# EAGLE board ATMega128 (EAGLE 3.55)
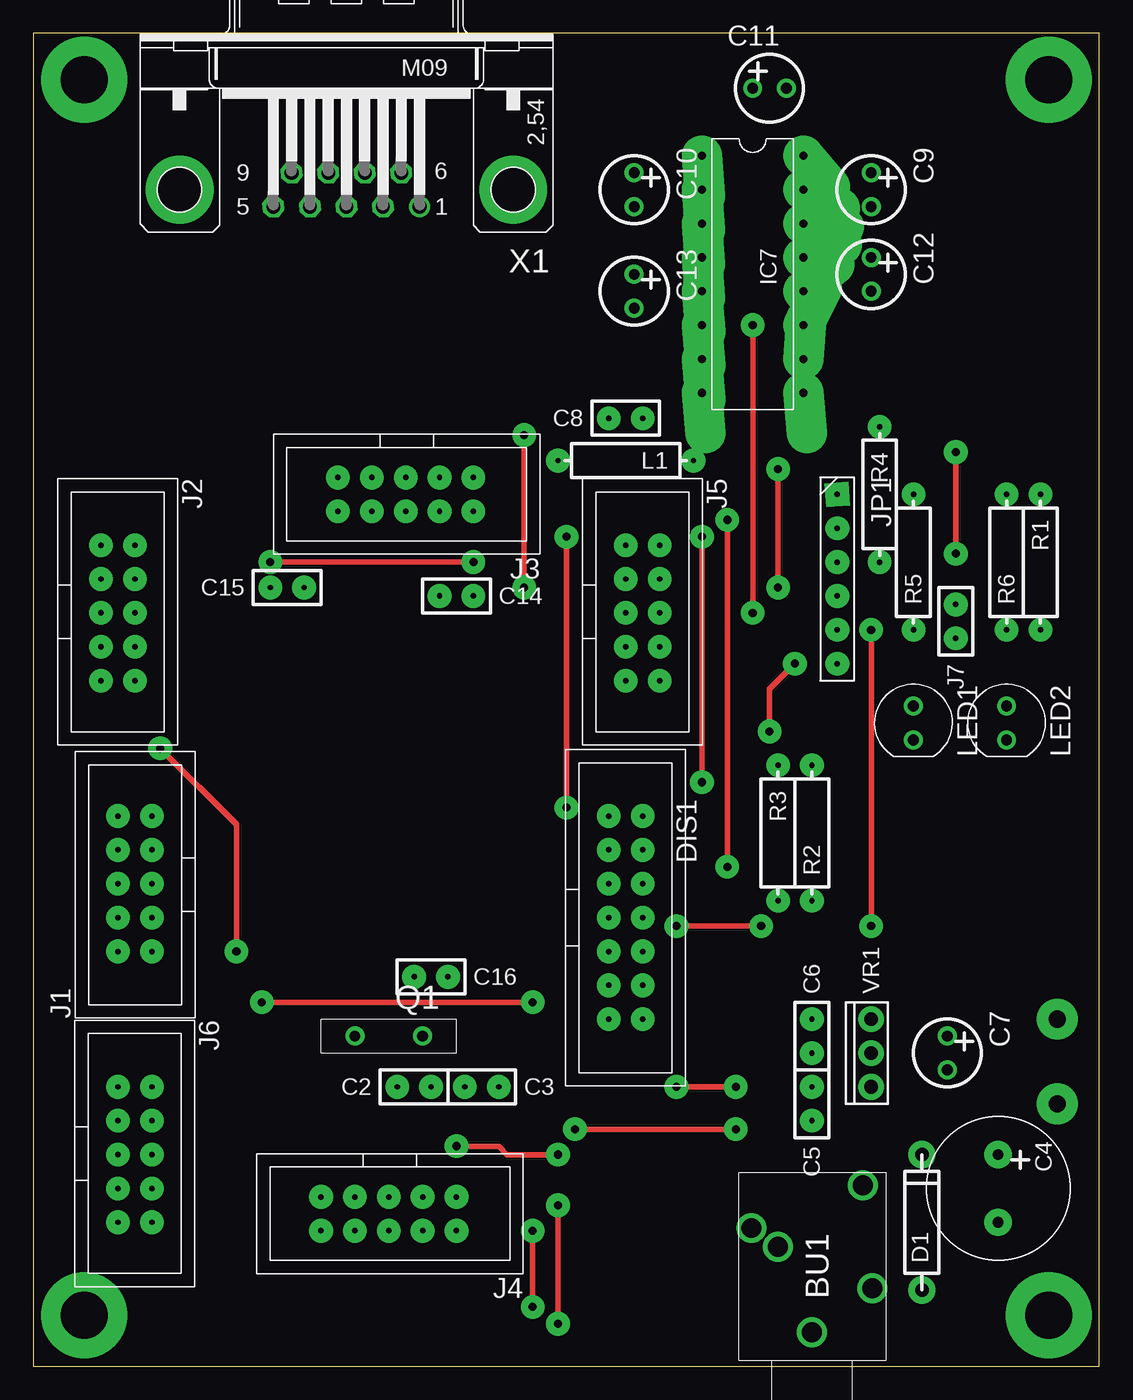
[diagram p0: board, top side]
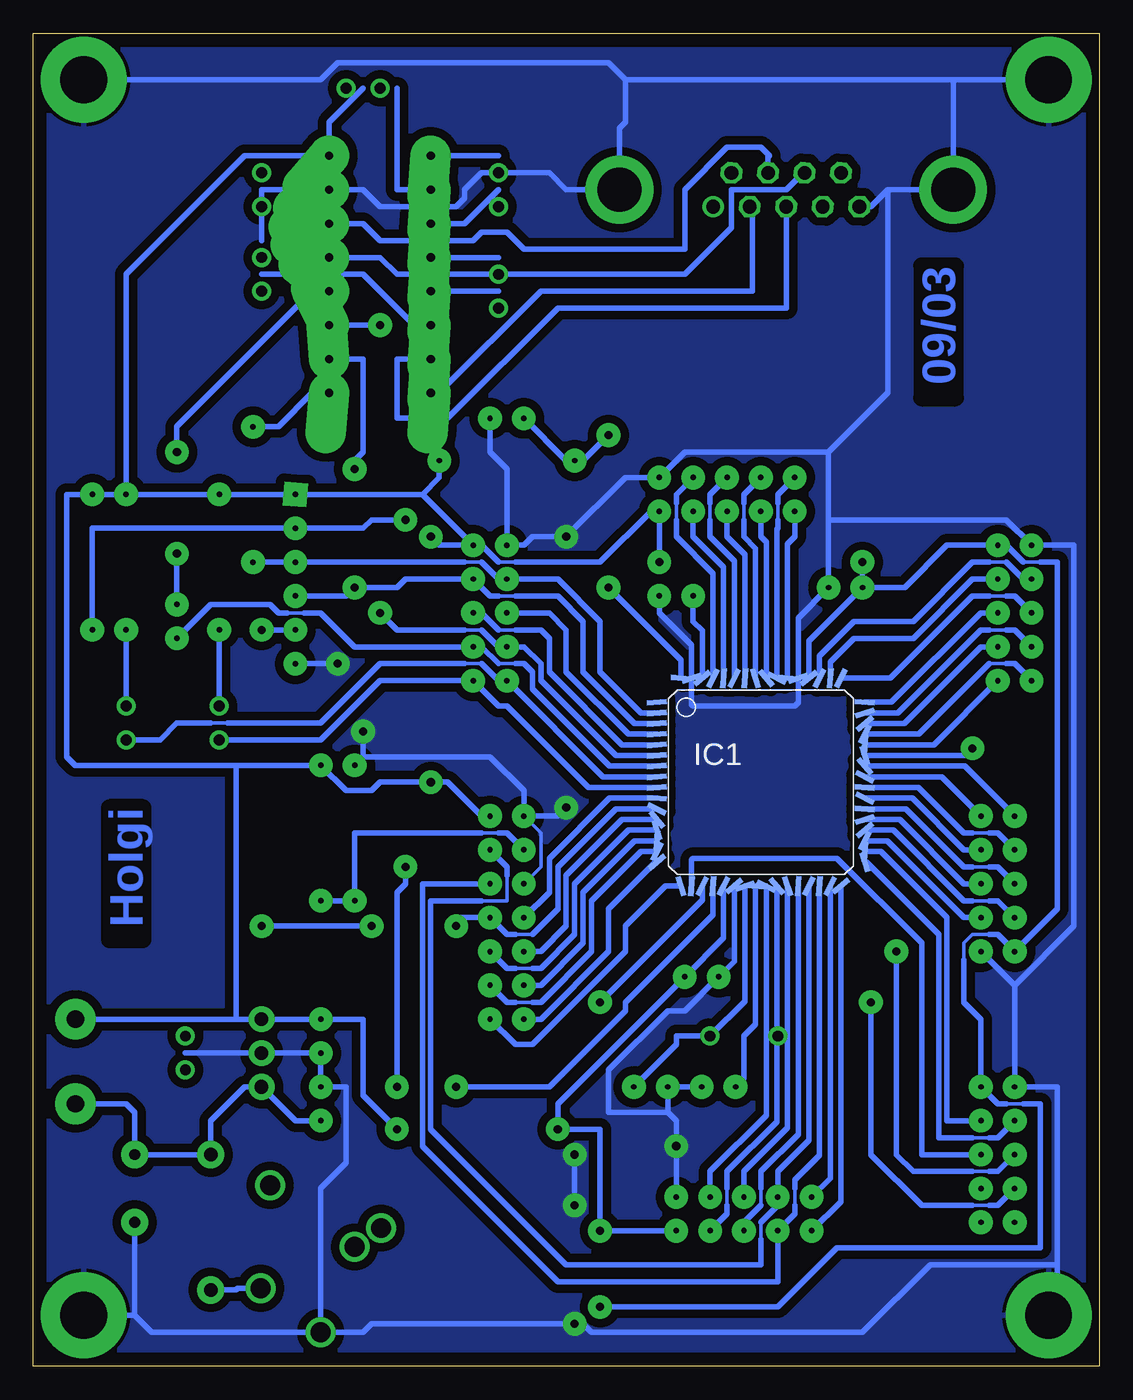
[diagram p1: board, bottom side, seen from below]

Size 79.99 x 100 mm. Coordinates in mm from the lower left corner, seen from the top.
Outline: 0,0 79.99,0 79.99,100 0,100 0,0
Copper layers used: Top, Bottom

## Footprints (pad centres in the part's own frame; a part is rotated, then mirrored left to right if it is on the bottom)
_3,5MM = drill 1.499 pad 2.184 round:  0,0;  3.302,-4.521;  7.823,4.521;  6.401,2.54;  11.024,-3.81
RM2,5 = drill 0.406 pad 1.778 round:  -1.27,0;  1.27,0
KO02 = drill 0.813 pad 2.032 round:  -2.54,0;  2.54,0
KO01 = drill 0.813 pad 1.422 round:  0,0;  2.54,0
O_1A = drill 1.016 pad 2.032 round:  -5.08,0;  5.08,0
7 = drill 0.406 pad 1.778 round:  0,0;  2.54,0;  5.08,0;  7.62,0;  10.16,0;  10.16,2.54;  7.62,2.54;  5.08,2.54;  2.54,2.54;  0,2.54;  12.7,0;  12.7,2.54;  15.24,0;  15.24,2.54
FP64 = smd 1.5 x 0.4 rotated 4.9:  -7.8,0.4 | smd 1.5 x 0.4 rotated 4.8:  -7.8,1.2 | smd 1.5 x 0.4 rotated 5:  -7.8,-0.4 | smd 1.5 x 0.4 rotated 4.3:  -7.8,-1.2;  -7.8,6 | smd 1.5 x 0.4 rotated 4.7:  -7.8,2;  -7.8,2.8 | smd 1.5 x 0.4 rotated 4.6:  -7.8,3.6;  7.8,-0.4 | smd 1.5 x 0.4 rotated 4.5:  -7.8,4.4 | smd 1.5 x 0.4 rotated 4.4:  -7.8,5.2 | smd 1.5 x 0.4 rotated 26.8:  -7.8,-2 | smd 1.5 x 0.4 rotated 49.3:  -7.8,-2.8 | smd 1.5 x 0.4 rotated 71.8:  -7.8,-3.6 | smd 1.5 x 0.4 rotated 94.3:  -7.8,-4.4 | smd 1.5 x 0.4 rotated 116.8:  -7.8,-5.2 | smd 1.5 x 0.4 rotated 139.3:  -7.8,-6 | smd 0.4 x 1.5 rotated 161.8:  -6,-7.8 | smd 0.4 x 1.5 rotated 184.3:  -5.2,-7.8 | smd 0.4 x 1.5 rotated 206.8:  -4.4,-7.8 | smd 0.4 x 1.5 rotated 4.4:  -3.6,-7.8 | smd 0.4 x 1.5 rotated 26.9:  -2.8,-7.8 | smd 0.4 x 1.5 rotated 49.4:  -2,-7.8 | smd 0.4 x 1.5 rotated 71.9:  -1.2,-7.8 | smd 0.4 x 1.5 rotated 94.4:  -0.4,-7.8 | smd 0.4 x 1.5 rotated 116.9:  0.4,-7.8 | smd 0.4 x 1.5 rotated 139.4:  1.2,-7.8 | smd 0.4 x 1.5 rotated 161.9:  2,-7.8 | smd 0.4 x 1.5 rotated 184.4:  2.8,-7.8 | smd 0.4 x 1.5 rotated 206.9:  3.6,-7.8 | smd 0.4 x 1.5 rotated 4.5:  4.4,-7.8 | smd 0.4 x 1.5 rotated 27:  5.2,-7.8 | smd 0.4 x 1.5 rotated 49.5:  6,-7.8 | smd 1.5 x 0.4 rotated 72:  7.8,-6 | smd 1.5 x 0.4 rotated 94.5:  7.8,-5.2 | smd 1.5 x 0.4 rotated 117:  7.8,-4.4 | smd 1.5 x 0.4 rotated 139.5:  7.8,-3.6 | smd 1.5 x 0.4 rotated 162:  7.8,-2.8 | smd 1.5 x 0.4 rotated 184.5:  7.8,-2 | smd 1.5 x 0.4 rotated 207:  7.8,-1.2 | smd 1.5 x 0.4 rotated 27.1:  7.8,0.4 | smd 1.5 x 0.4 rotated 49.6:  7.8,1.2 | smd 1.5 x 0.4 rotated 72.1:  7.8,2 | smd 1.5 x 0.4 rotated 94.6:  7.8,2.8 | smd 1.5 x 0.4 rotated 117.1:  7.8,3.6 | smd 1.5 x 0.4 rotated 139.6:  7.8,4.4 | smd 1.5 x 0.4 rotated 162.1:  7.8,5.2 | smd 1.5 x 0.4 rotated 184.6:  7.8,6 | smd 0.4 x 1.5 rotated 207.1:  6,7.8 | smd 0.4 x 1.5 rotated 4.7:  5.2,7.8;  -2.8,7.8 | smd 0.4 x 1.5 rotated 27.2:  4.4,7.8;  -3.6,7.8 | smd 0.4 x 1.5 rotated 49.7:  3.6,7.8;  -4.4,7.8 | smd 0.4 x 1.5 rotated 72.2:  2.8,7.8;  -5.2,7.8 | smd 0.4 x 1.5 rotated 94.7:  2,7.8;  -6,7.8 | smd 0.4 x 1.5 rotated 117.2:  1.2,7.8 | smd 0.4 x 1.5 rotated 139.7:  0.4,7.8 | smd 0.4 x 1.5 rotated 162.2:  -0.4,7.8 | smd 0.4 x 1.5 rotated 184.7:  -1.2,7.8 | smd 0.4 x 1.5 rotated 207.2:  -2,7.8
L-16B = drill 0.61 pad 3.048 offset:  -8.89,-3.81;  -6.35,-3.81;  6.35,-3.81;  8.89,-3.81;  -3.81,-3.81;  -1.27,-3.81;  3.81,-3.81;  1.27,-3.81;  8.89,3.81;  6.35,3.81;  3.81,3.81;  1.27,3.81;  -1.27,3.81;  -3.81,3.81;  -6.35,3.81;  -8.89,3.81
5 = drill 0.406 pad 1.778 round:  0,0;  2.54,0;  5.08,0;  7.62,0;  10.16,0;  10.16,2.54;  7.62,2.54;  5.08,2.54;  2.54,2.54;  0,2.54
MPER = drill 0.406 pad 1.778 round:  -1.27,0;  1.27,0
6 = drill 0.406 pad 1.778 square:  0,0 | drill 0.406 pad 1.778 round:  5.08,0;  10.16,0;  12.7,0;  7.62,0;  2.54,0
S04 = drill 0.406 pad 1.778 round:  -5.08,0;  5.08,0
D_5MM = drill 0.813 pad 1.422 round:  -1.27,0;  1.27,0
GEL = drill 1.295 pad 3.048 round:  0,0
ARZ_ST = drill 0.813 pad 1.422 round:  0,0;  5.08,0
HRUNG = drill 3.505 pad 6.452 round:  0,0
220A = drill 1.016 pad 1.93 round:  -2.54,0;  0,0;  2.54,0
9HP = drill 1.016 pad 1.6 octagon:  5.486,1.27;  2.743,1.27;  0,1.27;  -2.743,1.27;  4.115,-1.27;  1.372,-1.27;  -1.372,-1.27;  -4.115,-1.27 | drill 1.016 pad 1.6 round:  -5.486,1.27 | drill 3.302 pad 5.08 round:  -12.522,0;  12.522,0

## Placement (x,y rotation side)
BU1  BU_3,5MM  [_3,5MM]  58.42,2.54 90 top
C2  15p  [RM2,5]  28.57,20.95 180 top
C3  15p  [RM2,5]  33.66,20.95 0 top
C4  470u/25  [KO02]  72.39,13.34 270 top
C5  C100NK  [RM2,5]  58.42,19.68 270 top
C6  C100NK  [RM2,5]  58.42,24.77 90 top
C7  100u  [KO01]  68.58,24.77 270 top
C8  C100NK  [RM2,5]  44.45,71.12 180 top
C9  10u  [KO01]  62.87,89.53 270 top
C10  10u  [KO01]  45.09,89.53 270 top
C11  10u  [KO01]  53.98,95.89 0 top
C12  10u  [KO01]  62.87,83.19 270 top
C13  10u  [KO01]  45.09,81.92 270 top
C14  C100NK  [RM2,5]  31.75,57.78 0 top
C15  C100NK  [RM2,5]  19.05,58.42 180 top
C16  C100NK  [RM2,5]  29.84,29.21 0 top
D1  1N4001  [O_1A]  66.67,10.79 90 top
DIS1  LCD1  [7]  43.18,41.27 270 top
IC1  ATMEGA128  [FP64]  25.4,43.81 0 bottom
IC7  MAX232  [L-16B]  53.98,81.92 270 top
J1  8BITPORT  [5]  8.89,31.11 90 top
J2  8BITPORT  [5]  5.08,61.59 270 top
J3  8BITPORT  [5]  33.02,66.67 180 top
J4  8BITPORT  [5]  31.75,12.7 180 top
J5  8BITPORT  [5]  44.45,61.59 270 top
J6  8BITPORT  [5]  6.35,20.95 270 top
J7  JUMPER  [MPER]  69.22,55.88 270 top
JP1  PINHD-1X6  [6]  60.33,65.41 270 top
L1  100uH  [S04]  44.45,67.94 180 top
LED1  rot  [D_5MM]  66.04,48.26 270 top
LED2  grn  [D_5MM]  73.03,48.26 270 top
N4  +5V  [GEL]  76.83,26.04 0 top
N5  +Ub  [GEL]  76.83,19.68 0 top
Q1  8MHz  [ARZ_ST]  29.21,24.77 180 top
R1  47k  [S04]  75.56,60.33 270 top
R2  12k  [S04]  58.42,40.01 90 top
R3  1k  [S04]  55.88,40.01 270 top
R4  4k7  [S04]  63.5,65.41 270 top
R5  1k  [S04]  66.04,60.33 90 top
R6  1k  [S04]  73.03,60.33 90 top
U$30  BOHRUNG  [HRUNG]  76.2,96.52 0 top
U$31  BOHRUNG  [HRUNG]  76.2,3.81 0 top
U$32  BOHRUNG  [HRUNG]  3.81,3.81 0 top
U$33  BOHRUNG  [HRUNG]  3.81,96.52 0 top
VR1  7805  [220A]  62.87,23.5 90 top
X1  M09HP  [9HP]  23.5,88.27 180 top

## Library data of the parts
BU1 Q1 = bts
C2-C14 D1 L1 LED1 LED2 N4 N5 R1-R3 R5 R6 U$30-U$33 VR1 = holgnorm
C15 C16 DIS1 J1-J7 R4 = holg_plt
IC1 = ic_holg
IC7 = maxim
JP1 = PINHEAD
X1 = subd-a

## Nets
+5V: C6. C7. C9. C11. C15. C16. DIS1. IC1. IC7. J1. J2. J3. J4. J5. J6. JP1. L1. N4. R1. R2. R5. R6. VR1.
CTS: IC7. J7.
CTS_IN: IC7. X1.
CTSA: IC1. J5. J7.
GND: BU1. C2. C3. C4. C5. C6. C7. C8. C9. C12. C14. C15. C16. DIS1. IC1. IC7. J1. J2. J3. J4. J5. J6. JP1. R3. U$30. U$31. U$32. U$33. VR1. X1.
LCD_CS: DIS1. IC1. J4.
LCD_RS: DIS1. IC1. J4.
MISO: IC1. IC7. J5. JP1.
MOSI: IC1. J5. JP1. R4.
N$1: DIS1. IC1.
N$2: IC1. J6.
N$3: DIS1. IC1.
N$4: DIS1. IC1.
N$5: DIS1. IC1.
N$6: C3. IC1. Q1.
N$7: DIS1. IC1.
N$8: C2. IC1. Q1.
N$9: C12. IC7.
N$10: C11. IC7.
N$11: DIS1. IC1.
N$12: C10. IC7.
N$13: C13. IC7.
N$14: IC1. J1.
N$15: C10. IC7.
N$16: DIS1. IC1.
N$17: C13. IC7.
N$18: IC1. J1.
N$19: IC1. J1.
N$20: DIS1. R2. R3.
N$21: IC1. J1.
N$22: IC1. J1.
N$23: IC1. J1.
N$24: C8. IC1. L1.
N$25: IC1. J1.
N$26: IC1. J1.
N$27: C14. IC1.
N$28: IC1. J2.
N$29: IC1. J6.
N$30: IC1. J2.
N$31: IC1. J2.
N$32: IC1. J2.
N$33: IC1. J2.
N$34: IC1. J2.
N$35: IC1. J6.
N$36: LED1. R5.
N$37: LED2. R6.
N$38: IC1. J2.
N$39: IC1. J2.
N$40: IC1. J3.
N$41: IC1. J3.
N$42: C4. C5. D1. N5. VR1.
N$43: IC1. J3.
N$44: IC1. J3.
N$45: IC1. J3.
N$46: IC1. J3.
N$47: IC1. J3.
N$48: IC1. J3.
N$49: IC1. J4.
N$50: BU1. D1.
N$51: IC1. J4.
N$55: IC1. J5.
N$56: IC1. J4.
N$57: IC1. J4.
N$58: IC1. J5.
N$61: IC1. J5. LED2.
N$62: IC1. J5. LED1.
PG3: IC1. J6.
PG4: IC1. J6.
RESET: IC1. JP1. R1.
RTS: IC1. IC7. J5.
RTS_OUT: IC7. X1.
RXD: IC7. R4.
RXD1: IC1. J4.
RXD_IN: IC7. X1.
SCK: DIS1. IC1. JP1.
TXD1: IC1. J4.
TXD_OUT: IC7. X1.

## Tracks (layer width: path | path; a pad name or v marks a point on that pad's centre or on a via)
+5V  (via drill 0.61 pad 1.78)
  Top 0.406: v17.78,60.33 v33.02,60.33 | v37.47,4.45 v37.47,10.16 | v50.16,43.81 v50.16,62.23 | v40.64,17.78 v52.7,17.78
  Bottom 0.254: 45.09,60.33 43.81,60.33 | 4.45,60.33 5.71,60.33 | 10.16,30.48 10.16,31.75 9.53,32.38 8.26,32.38 | 5.71,19.68 6.99,19.68
  Bottom 0.406: 21.8,51.62 21.8,54.4 C15. | C15. 14.61,58.42 11.43,61.59 J2. 6.99,61.59 5.71,60.33 | 43.81,60.33 37.47,60.33 33.66,64.14 J3. v33.02,60.33 | J5. 46.35,61.59 45.09,60.33 | C15. v17.78,60.33 | 50.8,65.41 60.33,65.41 R5. R6. | 28.2,36.02 28.2,32.12 C16. 40.64,19.68 v40.64,17.78 37.47,17.78 v37.47,10.16 J4. | 4.45,60.33 3.17,60.33 3.17,34.29 J1. 7.62,32.38 8.26,32.38 | 10.16,30.48 10.16,27.3 8.89,26.04 J6. 7.62,19.68 6.99,19.68 | 5.71,19.68 4.45,19.68 4.45,8.89 19.68,8.89 24.13,4.45 v37.47,4.45 | 49.53,67.94 49.53,66.67 50.8,65.41 | 45.72,41.27 46.35,41.27 48.9,43.81 v50.16,43.81 53.98,43.81 54.61,43.18 56.52,43.18 R2. 64.77,45.09 | J5. 49.53,61.59 v50.16,62.23 | R6. 75.56,65.41 77.47,65.41 77.47,45.72 76.83,45.09 64.77,45.09 | 68.58,26.04 VR1. C6. 55.24,26.04 55.24,20.32 v52.7,17.78 | 68.58,26.04 N4. | 55.24,95.89 57.78,93.34 IC7. 62.87,90.81 64.14,90.81 73.03,81.92 R6. | 68.58,26.04 64.77,26.04 64.77,45.09 | J5. 50.8,65.41
CTS  (via drill 0.61 pad 1.78)
  Top 0.406: v69.22,60.96 v69.22,68.58
  Bottom 0.406: 69.22,57.15 v69.22,60.96 | 57.78,80.64 59.05,80.64 69.22,70.48 v69.22,68.58
CTS_IN
  Bottom 0.254: 44.45,81.92 45.72,81.92
  Bottom 0.406: 57.78,83.19 53.98,83.19 52.7,81.92 45.72,81.92 | 22.12,89.53 22.23,89.53 23.5,88.27 27.62,88.27 27.62,85.41 31.11,81.92 44.45,81.92
CTSA
  Bottom 0.254: 43.81,52.7 45.09,52.7 | 59.69,56.52 60.96,56.52
  Bottom 0.406: 33.2,45.02 36.76,45.02 42.55,50.8 42.55,52.07 43.18,52.7 43.81,52.7 | 45.09,52.7 46.35,53.98 46.99,53.98 55.88,53.98 58.42,56.52 59.69,56.52 | J7. 66.67,57.15 62.23,57.15 61.59,56.52 60.96,56.52
GND  (via drill 0.61 pad 1.78)
  Top 0.406: v39.37,3.17 v39.37,12.06 | v39.37,15.88 35.56,15.88 34.92,16.51 v31.75,16.51 | v40.01,62.23 v40.01,41.91 | v55.24,47.62 55.24,50.8 v57.15,52.7
  Bottom 0.254: 43.18,36.2 41.91,37.47 41.91,40.01 43.18,41.27 | 44.45,89.53 45.72,89.53
  Bottom 0.406: 20.32,63.5 6.99,63.5 5.08,61.59 1.91,61.59 1.91,33.02 6.35,28.57 | 20.32,63.5 20.32,58.42 22.6,56.14 22.6,51.62 22.6,49.79 22.86,49.53 30.48,49.53 30.6,49.65 30.6,51.62 30.6,54.09 33.02,56.52 C14. | 20.32,68.58 31.11,68.58 33.02,66.67 35.56,66.67 v40.01,62.23 42.55,62.23 43.18,61.59 44.45,61.59 44.45,67.31 45.72,68.58 45.72,71.12 | 20.32,63.5 20.32,68.58 | 29.84,20.95 32.38,20.95 32.38,19.05 | 27.4,36.02 27.4,30.39 28.57,29.21 31.11,26.67 32.38,26.67 36.83,22.23 36.83,19.05 32.38,19.05 | 32.38,19.05 31.75,18.41 v31.75,16.51 31.75,12.7 | 6.35,28.57 8.89,31.11 | 3.17,7.62 3.17,20.95 6.35,20.95 6.35,28.57 | 3.17,7.62 12.7,7.62 17.78,2.54 38.1,2.54 38.73,3.17 v39.37,3.17 54.61,3.17 55.24,2.54 58.42,2.54 | v39.37,12.06 v39.37,15.88 | v40.01,41.91 40.64,41.27 43.18,41.27 43.18,43.18 45.72,45.72 55.24,45.72 | 68.58,23.5 62.87,23.5 58.42,23.5 58.42,20.95 56.52,20.95 56.52,15.24 58.42,13.34 58.42,2.54 | 58.42,2.54 71.12,2.54 72.39,3.81 | 72.39,3.81 C4. | 62.87,84.45 62.87,88.27 57.78,88.27 55.24,88.27 53.98,87 48.26,87 47.62,87.63 47.62,88.27 46.35,89.53 45.72,89.53 | 10.79,96.52 10.97,96.34 X1. 15.88,88.27 | 10.79,96.52 U$33. | 10.79,96.52 35.56,96.52 | 18.01,87 17.14,87 15.88,88.27 | 44.45,89.53 41.27,89.53 40.01,88.27 36.02,88.27 36.02,92.89 35.56,93.34 35.56,96.52 | U$32. 3.81,6.35 3.17,6.99 3.17,7.62 | v57.15,52.7 60.33,52.7 | 55.24,45.72 55.88,45.09 | 55.24,45.72 v55.24,47.62 | 72.39,3.81 U$31. | U$30. 58.42,96.52 57.15,97.79 36.83,97.79 35.56,96.52 | 15.88,88.27 15.88,73.03 20.32,68.58
  pour Bottom (isolate 0.635): 0.64,0.64 0.64,99.69 79.38,99.69 79.38,0.64
LCD_CS
  Bottom 0.254: 22.86,12.06 22.86,13.34
  Bottom 0.406: 21,36.02 21,15.83 22.86,13.97 22.86,13.34 | 22.86,12.06 22.86,11.43 24.13,10.16 24.13,6.35 40.64,6.35 50.8,16.51 50.8,36.2 45.72,36.2
LCD_RS
  Bottom 0.254: 44.45,36.83 44.45,34.92 46.35,34.92 | 25.4,9.53 25.4,10.79
  Bottom 0.406: 21.8,36.02 21.8,16.93 24.13,14.61 24.13,12.7 24.13,12.06 25.4,10.79 | 45.72,38.73 44.45,37.47 44.45,36.83 | 46.35,34.92 50.16,34.92 50.16,17.78 40.01,7.62 25.4,7.62 25.4,9.53
MISO  (via drill 0.61 pad 1.78)
  Top 0.406: v55.88,58.42 v55.88,67.31
  Bottom 0.254: 43.81,57.78 45.09,57.78
  Bottom 0.406: 45.09,57.78 45.72,57.78 46.99,59.05 52.07,59.05 52.7,58.42 v55.88,58.42 56.52,57.78 60.33,57.78 | 33.2,48.22 34.88,48.22 38.73,52.07 38.73,55.88 40.64,57.78 43.81,57.78 | 57.78,75.56 55.24,75.56 55.24,68.58 55.88,67.94 v55.88,67.31
MOSI
  Bottom 0.254: 46.35,60.33 47.62,60.33
  Bottom 0.406: 33.2,49.02 34.41,49.02 37.47,52.07 37.47,55.88 40.64,59.05 44.45,59.05 45.09,59.05 46.35,60.33 | 47.62,60.33 60.33,60.33 R4.
N$1
  Bottom 0.406: 33.2,42.62 36.76,42.62 41.27,38.1 41.27,35.56 43.18,33.66
N$2
  Bottom 0.254: 8.26,17.14 9.53,17.14
  Bottom 0.406: 6.35,18.41 7.62,17.14 8.26,17.14 | 17.6,37.81 17.5,37.81 12.06,32.38 12.06,17.14 9.53,17.14
N$3
  Bottom 0.406: 33.2,41.02 35.82,41.02 40.01,36.83 40.01,33.02 41.91,31.11 43.18,31.11
N$4
  Bottom 0.254: 42.55,29.84 43.81,29.84
  Bottom 0.406: 45.72,31.11 44.45,29.84 43.81,29.84 | 33.2,40.22 35.35,40.22 39.37,36.2 39.37,32.38 41.91,29.84 42.55,29.84
N$5
  Bottom 0.406: 33.2,39.41 34.88,39.41 38.73,35.56 38.73,31.75 41.91,28.57 43.18,28.57
N$6
  Bottom 0.406: 26.6,36.02 26.6,27.38 29.21,24.77 31.75,24.77 31.75,24.13 C3.
N$7
  Bottom 0.254: 43.81,27.3 42.55,27.3
  Bottom 0.406: 45.72,28.57 44.45,27.3 43.81,27.3 | 33.2,38.62 34.41,38.62 38.1,34.92 38.1,31.11 41.91,27.3 42.55,27.3
N$8
  Bottom 0.406: 25.8,36.02 25.8,25.64 26.67,24.77 26.67,21.59 C2.
N$9
  Bottom 0.406: 62.87,81.92 55.24,81.92 51.44,78.11 50.16,78.11
N$10
  Bottom 0.406: 50.16,88.27 52.7,88.27 52.7,95.89
N$11
  Bottom 0.406: 33.2,37.81 33.3,37.81 36.83,34.29 36.83,31.11 41.91,26.04 43.18,26.04
N$12
  Bottom 0.406: 50.16,85.72 47.62,85.72 45.09,88.27
N$13
  Bottom 0.406: 45.09,80.64 50.16,80.64
N$14
  Bottom 0.406: 17.6,39.41 15.92,39.41 10.16,33.66 8.89,33.66
N$15
  Bottom 0.406: 45.09,90.81 50.16,90.81
N$16
  Bottom 0.406: 31.4,36.02 32.56,36.02 35.56,33.02 35.56,31.11 42.55,24.13 43.81,24.13 DIS1.
N$17
  Bottom 0.406: 45.09,83.19 50.16,83.19
N$18
  Bottom 0.254: 8.26,34.92 9.53,34.92
  Bottom 0.406: 6.35,33.66 7.62,34.92 8.26,34.92 | 17.6,40.22 15.45,40.22 10.16,34.92 9.53,34.92
N$19
  Bottom 0.406: 17.6,41.02 14.98,41.02 10.16,36.2 8.89,36.2
N$20
  Bottom 0.254: 45.09,40.01 46.35,40.01
  Bottom 0.406: 43.18,38.73 44.45,40.01 45.09,40.01 | 46.35,40.01 55.88,40.01 R3. 58.42,34.92
N$21
  Bottom 0.254: 8.26,37.47 9.53,37.47
  Bottom 0.406: 6.35,36.2 7.62,37.47 8.26,37.47 | 17.6,41.81 14.51,41.81 10.16,37.47 9.53,37.47
N$22
  Bottom 0.406: 17.6,42.62 14.04,42.62 10.16,38.73 8.89,38.73
N$23
  Bottom 0.254: 8.26,40.01 9.53,40.01
  Bottom 0.406: 17.6,43.41 13.57,43.41 10.16,40.01 9.53,40.01 | 6.35,38.73 7.62,40.01 8.26,40.01
N$24  (via drill 0.61 pad 1.78)
  Top 0.406: v36.83,58.42 v36.83,69.85
  Bottom 0.406: IC1. 31.4,52.99 v36.83,58.42 | v36.83,69.85 38.73,67.94 L1. 40.01,67.94 C8.
N$25
  Bottom 0.406: 17.6,44.22 11.83,44.22 8.89,41.27
N$26
  Bottom 0.406: 17.6,45.02 10.09,45.02 6.35,41.27
N$27
  Bottom 0.406: 29.8,51.62 29.8,55.2 30.48,55.88 30.48,57.78
N$28
  Bottom 0.254: 6.99,60.33 8.26,60.33
  Bottom 0.406: 21,51.62 21,53.3 18.41,55.88 13.97,55.88 9.53,60.33 8.26,60.33 | 5.08,59.05 5.71,59.05 6.99,60.33
N$29
  Bottom 0.406: 17.6,38.62 16.39,38.62 11.43,33.66 11.43,18.41 8.89,18.41
N$30
  Bottom 0.406: 20.2,51.62 20.2,52.83 18.41,54.61 13.97,54.61 9.53,59.05 7.62,59.05
N$31
  Bottom 0.254: 6.99,57.78 8.26,57.78
  Bottom 0.406: 5.08,56.52 6.35,57.78 6.99,57.78 | 19.4,51.62 15.7,51.62 9.53,57.78 8.26,57.78
N$32
  Bottom 0.406: 17.6,49.81 15.59,49.81 8.89,56.52 7.62,56.52
N$33
  Bottom 0.254: 6.99,55.24 8.26,55.24
  Bottom 0.406: 5.08,53.98 6.35,55.24 6.99,55.24 | 17.6,49.02 15.12,49.02 8.89,55.24 8.26,55.24
N$34
  Bottom 0.406: 17.6,48.22 14.65,48.22 8.89,53.98 7.62,53.98
N$35  (via drill 0.61 pad 1.78)
  Top 0.406: v9.53,46.35 15.24,40.64 v15.24,31.11
  Bottom 0.254: 8.26,14.61 9.53,14.61
  Bottom 0.406: 6.35,15.88 7.62,14.61 8.26,14.61 | v15.24,31.11 15.24,15.88 13.97,14.61 9.53,14.61 | 17.6,45.81 10.06,45.81 v9.53,46.35
N$36
  Bottom 0.406: 66.04,49.53 66.04,55.24
N$37
  Bottom 0.406: 73.03,49.53 73.03,55.24
N$38
  Bottom 0.254: 6.99,52.7 8.26,52.7
  Bottom 0.406: 17.6,47.41 13.54,47.41 8.26,52.7 | 5.08,51.44 6.35,52.7 6.99,52.7
N$39
  Bottom 0.406: 17.6,46.62 12.44,46.62 7.62,51.44
N$40
  Bottom 0.254: 31.75,63.5 31.75,64.77
  Bottom 0.406: 30.48,66.67 31.75,65.41 31.75,64.77 | 29,51.62 29,59.48 31.75,62.23 31.75,63.5
N$41
  Bottom 0.406: 28.2,51.62 28.2,59.95 30.48,62.23 30.48,64.14
N$42
  Bottom 0.406: C5. 60.33,18.41 62.87,20.95 64.14,20.95 66.67,18.41 D1. 72.39,15.88 72.39,19.05 73.03,19.68 N5.
N$43
  Bottom 0.254: 29.21,63.5 29.21,64.77
  Bottom 0.406: 27.94,66.67 29.21,65.41 29.21,64.77 | 27.4,51.62 27.4,60.42 29.21,62.23 29.21,63.5
N$44
  Bottom 0.406: 26.6,51.62 26.6,60.89 27.94,62.23 27.94,64.14
N$45
  Bottom 0.254: 26.67,63.5 26.67,64.77
  Bottom 0.406: 25.8,51.62 25.8,61.36 26.67,62.23 26.67,63.5 | 25.4,66.67 26.67,65.41 26.67,64.77
N$46
  Bottom 0.406: 25,51.62 25,61.83 25.4,62.23 25.4,64.14
N$47
  Bottom 0.254: 24.13,63.5 24.13,64.77
  Bottom 0.406: 24.2,51.62 24.2,62.8 24.13,62.87 24.13,63.5 | 22.86,66.67 24.13,65.41 24.13,64.77
N$48
  Bottom 0.406: 23.4,51.62 23.4,61.69 22.86,62.23 22.86,64.14
N$49
  Bottom 0.406: 25,36.02 25,18.82 29.21,14.61 29.21,12.7
N$50
  Bottom 0.406: 62.94,5.84 64.64,5.84 64.77,5.71 66.67,5.71
N$51
  Bottom 0.254: 27.94,12.06 27.94,13.34
  Bottom 0.406: 24.2,36.02 24.2,18.34 27.94,14.61 27.94,13.34 | 29.21,10.16 27.94,11.43 27.94,12.06
N$55
  Bottom 0.406: 33.2,47.41 35.35,47.41 40.01,52.07 40.01,55.24 41.27,56.52 44.45,56.52
N$56
  Bottom 0.406: 20.2,36.02 20.2,14.09 21.59,12.7
N$57
  Bottom 0.406: 19.4,36.02 19.4,12.35 21.59,10.16
N$58
  Bottom 0.254: 43.81,55.24 45.09,55.24
  Bottom 0.406: 33.2,46.62 35.82,46.62 41.27,52.07 41.27,54.61 41.91,55.24 43.81,55.24 | 46.99,56.52 46.35,56.52 45.09,55.24
N$61
  Bottom 0.254: 46.35,52.7 47.62,52.7 | 65.41,48.26 66.67,48.26
  Bottom 0.406: 33.2,44.22 37.23,44.22 44.45,51.44 45.09,51.44 46.35,52.7 | 47.62,52.7 53.98,52.7 58.42,48.26 65.41,48.26 | 66.67,48.26 69.22,48.26 70.48,46.99 LED2.
N$62
  Bottom 0.406: 33.2,43.41 38.34,43.41 44.45,49.53 45.09,49.53 46.99,51.44 53.98,51.44 58.42,46.99 LED1.
PG3
  Bottom 0.406: 30.6,36.02 30.6,37.98 30.48,38.1 19.68,38.1 13.34,31.75 13.34,15.88 8.89,15.88
PG4  (via drill 0.61 pad 1.78)
  Top 0.406: v17.14,27.3 v37.47,27.3
  Bottom 0.254: 8.26,12.06 9.53,12.06
  Bottom 0.406: 6.35,13.34 7.62,12.06 8.26,12.06 | 29.8,36.02 29.8,34.97 v37.47,27.3 | 9.53,12.06 13.34,12.06 17.14,15.88 v17.14,27.3
RESET  (via drill 0.61 pad 1.78)
  Top 0.406: v52.07,37.47 v52.07,63.5 | v48.26,20.95 v52.7,20.95
  Bottom 0.406: 29,36.02 29,33.87 35.56,27.3 35.56,26.67 41.27,20.95 v48.26,20.95 | v52.07,63.5 54.61,63.5 55.24,62.87 JP1. 75.56,62.87 R1. | v52.7,20.95 52.7,35.56 52.07,36.2 v52.07,37.47
RTS  (via drill 0.61 pad 1.78)
  Top 0.406: v53.98,56.52 v53.98,78.11
  Bottom 0.254: 46.35,55.24 47.62,55.24
  Bottom 0.406: 33.2,45.81 36.29,45.81 41.91,51.44 41.91,52.7 43.18,53.98 44.45,53.98 45.09,53.98 46.35,55.24 | 47.62,55.24 52.7,55.24 v53.98,56.52 | v53.98,78.11 57.78,78.11
RTS_OUT
  Bottom 0.406: 24.87,89.53 24.87,90.7 24.77,90.81 25.4,91.44 27.94,91.44 31.11,88.27 31.11,83.82 43.18,83.82 44.45,85.09 46.35,85.09 46.99,84.45 53.98,84.45 55.24,85.72 57.78,85.72
RXD
  Bottom 0.406: 57.78,73.03 59.05,73.03 61.59,70.48 63.5,70.48
RXD1
  Bottom 0.406: 23.4,36.02 23.4,17.88 26.67,14.61 26.67,12.7
RXD_IN
  Bottom 0.406: 26.24,87 26.04,86.79 26.04,80.64 41.91,80.64 49.53,73.03 50.16,73.03
SCK  (via drill 0.61 pad 1.78)
  Top 0.406: v48.26,33.02 v54.61,33.02 | v62.87,33.02 v62.87,55.24
  Bottom 0.254: 42.55,32.38 43.81,32.38
  Bottom 0.406: 43.81,32.38 44.45,32.38 45.72,33.66 48.26,33.66 v48.26,33.02 | 33.2,41.81 36.29,41.81 40.64,37.47 40.64,34.29 42.55,32.38 | v62.87,55.24 60.33,55.24 | v54.61,33.02 v62.87,33.02
TXD1
  Bottom 0.254: 25.4,12.06 25.4,13.34
  Bottom 0.406: 22.6,36.02 22.6,17.41 25.4,14.61 25.4,13.34 | 26.67,10.16 26.67,10.79 25.4,12.06
TXD_OUT
  Bottom 0.406: 23.5,87 23.5,79.38 40.64,79.38 48.9,71.12 52.7,71.12 52.7,75.56 50.16,75.56

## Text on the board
Bottom: 09/03 | Holgi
